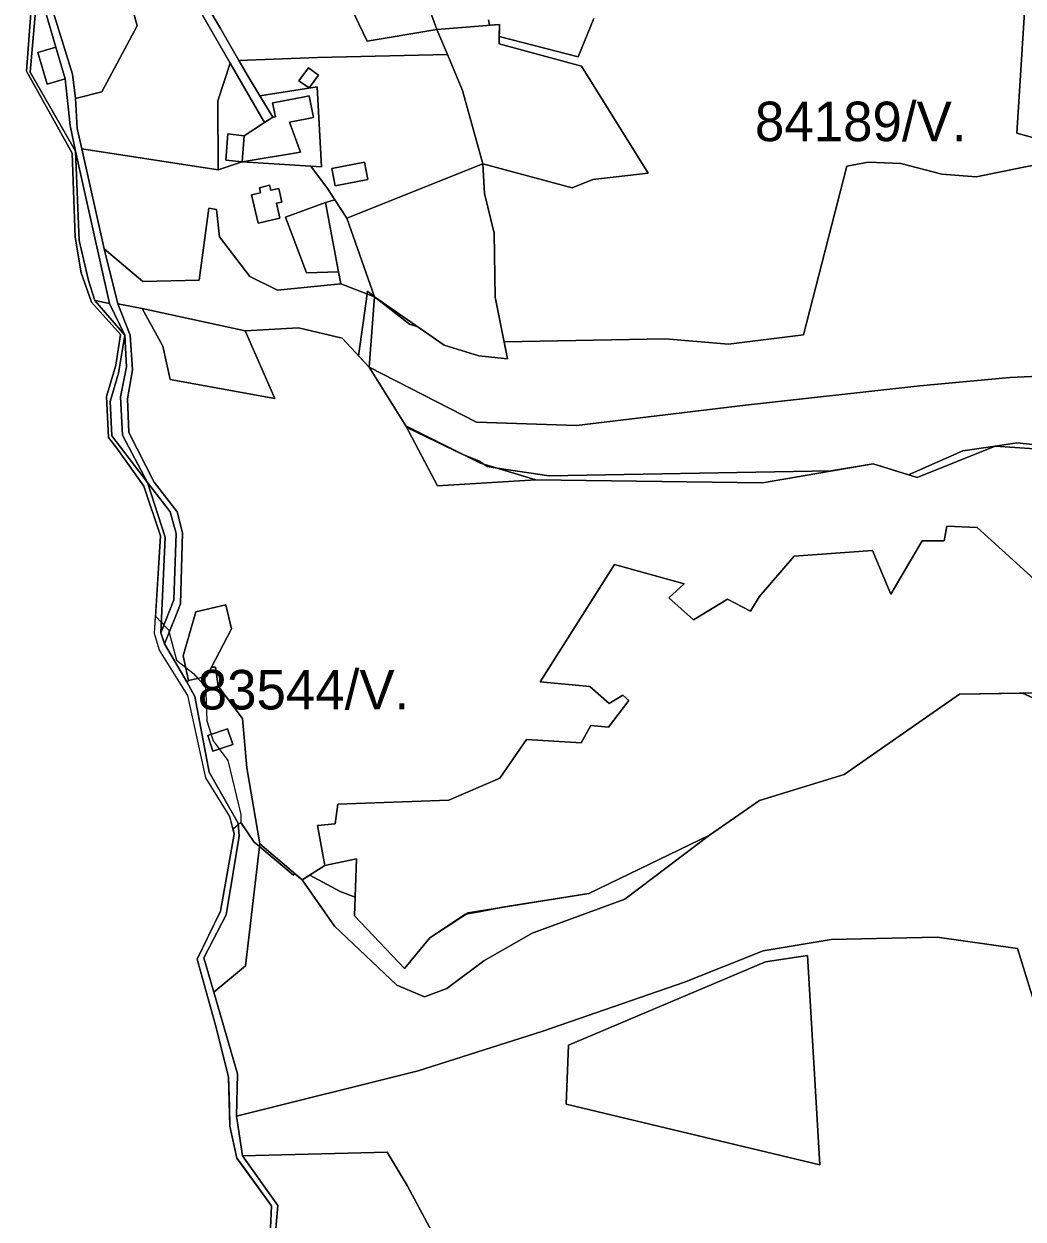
# Model space of a CAD drawing. Extents: x -477304 to -465429, y -1159113 to -1149210.
# Drawn here: x -476570.9 to -476191.6, y -1153194.5 to -1152741 of the extents above; entities that cross this region are included whole.
import ezdxf

# ---------------------------------------------------------------- set-up
doc = ezdxf.new("R2010")
doc.units = 0
for name, color, linetype in [('BPEJ_s', 7, 'Continuous'), ('orna_s', 7, 'Continuous'), ('ostatni_s', 7, 'Continuous'), ('PUPFL_s', 7, 'Continuous'), ('trav_porost_s', 7, 'Continuous'), ('voda_s', 7, 'Continuous'), ('zahrada_s', 7, 'Continuous')]:
    doc.layers.add(name, color=color, linetype=linetype)

msp = doc.modelspace()

# ---------------------------------------------------------------- linework, layer by layer
at = {"layer": 'BPEJ_s'}
for points in [[(-476183, -1152785.5), (-476194, -1152782.5), (-476189, -1152702.5)], [(-476189, -1152702.5), (-476194, -1152782.5), (-476183, -1152785.5)], [(-476567.81, -1152731.72), (-476569.91, -1152758.93), (-476552.56, -1152790.08), (-476551.47, -1152822.01), (-476549.14, -1152835.44), (-476545.27, -1152846.67), (-476534.26, -1152858.87), (-476536.03, -1152870.47), (-476539.49, -1152882.43), (-476538.76, -1152897.9), (-476535.65, -1152901.99), (-476525.32, -1152916.42), (-476519.08, -1152935.21), (-476520.9, -1152965.69), (-476520.9, -1152965.69), (-476518.68, -1152968.1), (-476518.45, -1152968.34), (-476517.71, -1152969.14), (-476516, -1152971), (-476515.74, -1152971.98), (-476513, -1152982.5), (-476509.45, -1152985.23), (-476506.5, -1152987.5), (-476504.83, -1152989.35), (-476502, -1152992.5), (-476501.71, -1152998.04), (-476501.5, -1153005.5), (-476499.79, -1153010.62), (-476499, -1153013), (-476496.71, -1153016.13), (-476493.5, -1153020.5), (-476488.5, -1153041), (-476488.5, -1153044), (-476483.5, -1153051.5), (-476481.47, -1153053.19), (-476468.5, -1153064), (-476468.07, -1153063.46), (-476465.27, -1153065.84), (-476462.38, -1153064), (-476450.8, -1153070.2), (-476445.15, -1153072.31), (-476445.37, -1153079.45), (-476426.41, -1153099.42), (-476416.78, -1153087.77), (-476403.23, -1153078.87), (-476398.04, -1153077.88), (-476389.27, -1153076.21), (-476356.49, -1153071.02), (-476310.66, -1153048.87), (-476291.65, -1153035.67), (-476259.6, -1153025.84), (-476215.79, -1152995.34), (-476191.88, -1152994.93)], [(-476354.5, -1152739), (-476360.5, -1152753.5), (-476390.47, -1152745.78), (-476390.33, -1152741.26), (-476394.13, -1152741.56), (-476394.5, -1152739.5)], [(-476394.5, -1152739.5), (-476394.13, -1152741.56), (-476390.33, -1152741.26), (-476390.47, -1152745.78), (-476360.5, -1152753.5), (-476354.5, -1152739)], [(-476145.5, -1152905), (-476194, -1152900), (-476202.3, -1152901.21), (-476214.5, -1152903), (-476235.1, -1152912.16), (-476248.57, -1152907.9), (-476264.62, -1152910.67), (-476371.5, -1152912.5), (-476391.22, -1152909.56), (-476395, -1152909), (-476396.57, -1152907.95), (-476398, -1152907), (-476403.3, -1152904.79), (-476404, -1152904.5), (-476425.51, -1152894.21), (-476425.88, -1152893.51), (-476439.81, -1152871.28), (-476443.85, -1152866.93), (-476442.15, -1152854.51), (-476440.64, -1152843.5), (-476440.5, -1152842.5), (-476437.82, -1152844.59), (-476424.5, -1152855), (-476421.3, -1152856.02), (-476411.35, -1152862.9), (-476398.18, -1152866.97), (-476387.29, -1152868.06), (-476388.56, -1152861.72), (-476327.5, -1152860.5), (-476303.5, -1152862.5), (-476275, -1152859), (-476258.5, -1152795), (-476250.5, -1152793.5), (-476238, -1152794), (-476222.5, -1152798), (-476209.5, -1152799), (-476182, -1152793.5)], [(-476182, -1152793.5), (-476209.5, -1152799), (-476222.5, -1152798), (-476238, -1152794), (-476250.5, -1152793.5), (-476258.5, -1152795), (-476275, -1152859), (-476303.5, -1152862.5), (-476327.5, -1152860.5), (-476388.56, -1152861.72), (-476387.29, -1152868.06)], [(-476387.29, -1152868.06), (-476398.18, -1152866.97), (-476411.35, -1152862.9), (-476421.3, -1152856.02), (-476424.5, -1152855), (-476437.82, -1152844.59), (-476440.5, -1152842.5), (-476440.64, -1152843.5), (-476442.15, -1152854.51), (-476443.85, -1152866.93), (-476439.81, -1152871.28), (-476425.88, -1152893.51), (-476425.51, -1152894.21), (-476404, -1152904.5), (-476403.3, -1152904.79), (-476398, -1152907), (-476396.57, -1152907.95), (-476395, -1152909), (-476391.22, -1152909.56), (-476371.5, -1152912.5), (-476264.62, -1152910.67), (-476248.57, -1152907.9), (-476235.1, -1152912.16), (-476214.5, -1152903), (-476202.3, -1152901.21), (-476194, -1152900), (-476145.5, -1152905)], [(-476187.7, -1152996.9), (-476191.88, -1152994.93), (-476215.79, -1152995.34), (-476259.6, -1153025.84), (-476291.65, -1153035.67), (-476310.66, -1153048.87), (-476356.49, -1153071.02), (-476389.27, -1153076.21), (-476398.04, -1153077.88), (-476403.23, -1153078.87), (-476416.78, -1153087.77), (-476426.41, -1153099.42), (-476445.37, -1153079.45), (-476445.15, -1153072.31), (-476450.8, -1153070.2), (-476462.38, -1153064), (-476465.27, -1153065.84), (-476468.07, -1153063.46), (-476468.5, -1153064), (-476481.47, -1153053.19), (-476483.5, -1153051.5), (-476488.5, -1153044), (-476489.53, -1153044.88), (-476491.48, -1153046.55), (-476491.01, -1153048.45), (-476496.24, -1153077.74), (-476501.28, -1153088.1), (-476505.09, -1153095.93), (-476503.7, -1153100.91), (-476498.11, -1153120.94), (-476493.2, -1153140.58), (-476492.88, -1153151.81), (-476492.67, -1153159.21), (-476490.01, -1153171.43), (-476488.09, -1153174.09), (-476476.96, -1153189.51), (-476477.29, -1153197.87)], [(-476191.88, -1152994.93), (-476187.7, -1152996.9)]]:
    msp.add_lwpolyline(points, dxfattribs=at)
msp.add_lwpolyline([(-476489.53, -1153044.88), (-476491.48, -1153046.55), (-476492.65, -1153041.77), (-476501.85, -1153027.08), (-476508.63, -1152995.85), (-476519.41, -1152978.6), (-476521.3, -1152972.35), (-476520.9, -1152965.69), (-476520.9, -1152965.69), (-476518.68, -1152968.1), (-476518.45, -1152968.34), (-476517.71, -1152969.14), (-476516, -1152971), (-476515.74, -1152971.98), (-476513, -1152982.5), (-476509.45, -1152985.23), (-476506.5, -1152987.5), (-476504.83, -1152989.35), (-476502, -1152992.5), (-476501.71, -1152998.04), (-476501.5, -1153005.5), (-476499.79, -1153010.62), (-476499, -1153013), (-476496.71, -1153016.13), (-476493.5, -1153020.5), (-476488.5, -1153041), (-476488.5, -1153044)], close=True, dxfattribs=at)
at = {"layer": 'orna_s'}
for points in [[(-476424.8, -1152645.4), (-476425.84, -1152701.17), (-476421.11, -1152723.99), (-476414.17, -1152743.15), (-476440.62, -1152747.55), (-476448.07, -1152731.86), (-476492.05, -1152735.81), (-476492.35, -1152704.81), (-476478.13, -1152702.4), (-476471.19, -1152696.63), (-476478.48, -1152696.5), (-476472.81, -1152648.4), (-476467.38, -1152631.32)], [(-476448.35, -1152814.68), (-476396.66, -1152794.08), (-476396.1, -1152805.37), (-476392.4, -1152820.38), (-476391.98, -1152844.66), (-476387.29, -1152868.06), (-476398.18, -1152866.97), (-476411.35, -1152862.9), (-476437.82, -1152844.59)]]:
    msp.add_lwpolyline(points, close=True, dxfattribs=at)
at = {"layer": 'ostatni_s'}
for points in [[(-476562.08, -1152763.89), (-476555.2, -1152761.87), (-476553.29, -1152779.52), (-476551.25, -1152789.35), (-476568.49, -1152759.38), (-476566.13, -1152731.75), (-476570.87, -1152716.42), (-476569.14, -1152714.66), (-476562.37, -1152717.06), (-476563.56, -1152733.44), (-476558.73, -1152749.83), (-476565.61, -1152751.85)], [(-476555.2, -1152761.87), (-476562.08, -1152763.89), (-476565.61, -1152751.85), (-476558.73, -1152749.83)], [(-476466.47, -1152762.6), (-476462.89, -1152757.73), (-476459.06, -1152760.54), (-476462.64, -1152765.31)], [(-476475.67, -1152770.88), (-476465.06, -1152768.82), (-476462.66, -1152768.36), (-476461, -1152776.59), (-476463.47, -1152777.08), (-476470.03, -1152778.31), (-476465.88, -1152789.68), (-476488.08, -1152793.41), (-476487.31, -1152783.47), (-476479.54, -1152778.48), (-476476.4, -1152776.47), (-476475.41, -1152776.32), (-476476.46, -1152771.03)], [(-476488.08, -1152793.41), (-476494.22, -1152792.73), (-476493.46, -1152782.8), (-476487.31, -1152783.47)], [(-476543.9, -1152846.04), (-476546.3, -1152838.37), (-476549.86, -1152823.16), (-476551.25, -1152789.35), (-476538.37, -1152847.07)], [(-476440.34, -1152800.01), (-476452.79, -1152802.42), (-476454.04, -1152795.94), (-476441.59, -1152793.53)], [(-476477.16, -1152804.14), (-476474.15, -1152803.45), (-476472.95, -1152808.61), (-476474.96, -1152809.07), (-476473.78, -1152814.69), (-476481.9, -1152816.63), (-476484.43, -1152805.9), (-476481.01, -1152805.07), (-476481.45, -1152803.19), (-476477.6, -1152802.25)], [(-476450.63, -1152839.62), (-476451.48, -1152835.09), (-476456.38, -1152808.8), (-476452.87, -1152807.77), (-476448.35, -1152814.68), (-476437.82, -1152844.59)], [(-476538.37, -1152847.07), (-476532.5, -1152859.18), (-476543.9, -1152846.04)], [(-476523.97, -1152915.05), (-476537.49, -1152897.27), (-476538.07, -1152884.24), (-476534.94, -1152873.49), (-476532.5, -1152859.18), (-476531.99, -1152871.1), (-476534.24, -1152882.48), (-476533.47, -1152897.09)], [(-476513.07, -1152934.44), (-476513.99, -1152959.51), (-476518.86, -1152972.11), (-476517.21, -1152935.73), (-476523.97, -1152915.05), (-476515.36, -1152926.21)], [(-476501.52, -1152988.65), (-476508.42, -1152990.11), (-476510.39, -1152980.77), (-476505.59, -1152964.16), (-476494.29, -1152961.41), (-476492.06, -1152970.58), (-476499.63, -1152985.05)], [(-476486.31, -1153023.31), (-476481.35, -1153052.13), (-476486.82, -1153098.41), (-476498.77, -1153108.38), (-476502.52, -1153095.43), (-476494.09, -1153079.04), (-476489.13, -1153049.27), (-476489.58, -1153044.29), (-476500.58, -1153024.93), (-476505.96, -1152996.25), (-476509.04, -1152990.71), (-476508.42, -1152990.11), (-476501.52, -1152988.65), (-476499.63, -1152985.05), (-476498.11, -1152985.06), (-476497.14, -1152992.25), (-476487.94, -1153004.53)], [(-476499.13, -1153016.94), (-476491.63, -1153014.42), (-476493.61, -1153008.54), (-476501.11, -1153011.06)], [(-476501.11, -1153011.06), (-476493.61, -1153008.54), (-476491.63, -1153014.42), (-476499.13, -1153016.94)]]:
    msp.add_lwpolyline(points, close=True, dxfattribs=at)
for points in [[(-476506.9, -1152724.73), (-476496.31, -1152742.79), (-476489.28, -1152754.92), (-476485.79, -1152760.93), (-476481.32, -1152768.33), (-476476.4, -1152776.47), (-476479.54, -1152778.48), (-476492.61, -1152755.92), (-476512.6, -1152721.2)], [(-476561.07, -1152732.37), (-476552.44, -1152760.14), (-476551.29, -1152769.3), (-476550.67, -1152780.67), (-476548.94, -1152788.49), (-476540.39, -1152826.33), (-476535.22, -1152847.27), (-476530.49, -1152859.18), (-476529.59, -1152872.29), (-476531.58, -1152883.35), (-476531.08, -1152896.12), (-476521.42, -1152914.86), (-476512.68, -1152926.12), (-476510.7, -1152934.15), (-476511.4, -1152961.06), (-476513.15, -1152965.59), (-476517.45, -1152976.19), (-476518.86, -1152972.11), (-476513.99, -1152959.51), (-476513.07, -1152934.44), (-476515.36, -1152926.21), (-476523.97, -1152915.05), (-476533.47, -1152897.09), (-476534.24, -1152882.48), (-476531.99, -1152871.1), (-476532.5, -1152859.18), (-476538.37, -1152847.07), (-476551.25, -1152789.35), (-476553.29, -1152779.52), (-476555.2, -1152761.87), (-476558.73, -1152749.83), (-476563.56, -1152733.44)]]:
    msp.add_lwpolyline(points, dxfattribs=at)
at = {"layer": 'PUPFL_s'}
for points in [[(-476163.87, -1152873.72), (-476196.63, -1152875.18), (-476230.81, -1152878.34), (-476296.98, -1152885.68), (-476361.17, -1152893.44), (-476399.05, -1152892.12), (-476439.81, -1152871.28), (-476437.82, -1152844.59), (-476411.35, -1152862.9), (-476398.18, -1152866.97), (-476387.29, -1152868.06), (-476391.98, -1152844.66), (-476392.4, -1152820.38), (-476396.1, -1152805.37), (-476396.66, -1152794.08), (-476362.76, -1152803.27), (-476354.95, -1152800.05), (-476333.91, -1152797.71), (-476359.23, -1152757.08), (-476390.55, -1152748.6), (-476390.33, -1152741.26), (-476414.17, -1152743.15), (-476421.11, -1152723.99)], [(-476183.76, -1153124.12), (-476193.73, -1153091.86), (-476224.3, -1153087.6), (-476264.53, -1153088.47), (-476290.31, -1153092.75), (-476320.21, -1153104.57), (-476373.93, -1153123.2), (-476421.24, -1153138.32), (-476490.14, -1153155.42), (-476489.78, -1153139.43), (-476498.77, -1153108.38), (-476486.82, -1153098.41), (-476481.35, -1153052.13), (-476465.27, -1153065.84), (-476452.95, -1153083.34), (-476429.35, -1153105.72), (-476418.88, -1153110.2), (-476410.32, -1153107.01), (-476396.35, -1153096.51), (-476377.93, -1153086.03), (-476342.8, -1153073.18), (-476310.66, -1153048.87), (-476291.65, -1153035.67), (-476259.6, -1153025.84), (-476215.79, -1152995.34), (-476178.14, -1152994.7)]]:
    msp.add_lwpolyline(points, dxfattribs=at)
for points in [[(-476488.08, -1152793.41), (-476497.12, -1152796.4), (-476497.26, -1152770.21), (-476492.61, -1152755.92), (-476479.54, -1152778.48), (-476487.31, -1152783.47), (-476493.46, -1152782.8), (-476494.22, -1152792.73)], [(-476485.16, -1152836.89), (-476474.63, -1152842.07), (-476450.63, -1152839.62), (-476437.82, -1152844.59), (-476439.81, -1152871.28), (-476450.03, -1152860.28), (-476466.6, -1152856.3), (-476486.86, -1152857.51), (-476525.95, -1152849.05), (-476535.22, -1152847.27), (-476540.39, -1152826.33), (-476525.69, -1152838.74), (-476504.36, -1152838.24), (-476500.64, -1152810.93), (-476497.73, -1152811.49), (-476496.61, -1152821.85)], [(-476290.59, -1152915.16), (-476376.53, -1152913.98), (-476397.58, -1152907.65), (-476425.88, -1152893.51), (-476439.81, -1152871.28), (-476399.05, -1152892.12), (-476361.17, -1152893.44), (-476296.98, -1152885.68), (-476230.81, -1152878.34), (-476196.63, -1152875.18), (-476163.87, -1152873.72), (-476141.62, -1152874.59), (-476110.83, -1152874.53), (-476094.77, -1152885.67), (-476096.02, -1152886.18), (-476127.83, -1152880.43), (-476142, -1152889.67), (-476142.53, -1152905.27), (-476202.3, -1152901.21), (-476231.89, -1152913.17), (-476248.57, -1152907.9)], [(-476397.58, -1152907.65), (-476376.53, -1152913.98), (-476413.93, -1152916.28), (-476425.88, -1152893.51)], [(-476402.31, -1153078.27), (-476356.49, -1153071.02), (-476310.66, -1153048.87), (-476342.8, -1153073.18), (-476377.93, -1153086.03), (-476396.35, -1153096.51), (-476410.32, -1153107.01), (-476418.88, -1153110.2), (-476429.35, -1153105.72), (-476452.95, -1153083.34), (-476465.27, -1153065.84), (-476456.65, -1153060.35), (-476444.69, -1153057.83), (-476445.37, -1153079.45), (-476426.41, -1153099.42), (-476416.78, -1153087.77)], [(-476333.46, -1153213.17), (-476348.76, -1153204.42), (-476350.46, -1153205.59), (-476354.47, -1153208.34), (-476409.37, -1153211.76), (-476425.36, -1153181.8), (-476432.95, -1153169.09), (-476487.9, -1153170.54), (-476490.14, -1153155.42), (-476421.24, -1153138.32), (-476373.93, -1153123.2), (-476320.21, -1153104.57), (-476290.31, -1153092.75), (-476264.53, -1153088.47), (-476224.3, -1153087.6), (-476193.73, -1153091.86), (-476183.76, -1153124.12), (-476173.13, -1153165.8), (-476161.23, -1153190.7), (-476157.59, -1153196.3), (-476305.47, -1153241.12), (-476320.95, -1153249.89), (-476326.21, -1153247.82), (-476320.61, -1153240.93)], [(-476273.43, -1153094.46), (-476289.47, -1153096.9), (-476364.18, -1153128.52), (-476365, -1153150.9), (-476268.81, -1153173.98)], [(-476365, -1153150.9), (-476364.18, -1153128.52), (-476289.47, -1153096.9), (-476273.43, -1153094.46), (-476268.81, -1153173.98)], [(-476425.36, -1153181.8), (-476409.37, -1153211.76), (-476433.36, -1153199.63), (-476439.63, -1153201.87), (-476474.05, -1153228.49), (-476476.82, -1153215.58), (-476474.44, -1153189.34), (-476487.9, -1153170.54), (-476432.95, -1153169.09)]]:
    msp.add_lwpolyline(points, close=True, dxfattribs=at)
at = {"layer": 'trav_porost_s'}
for points in [[(-476548.59, -1152723.31), (-476544.56, -1152718.44), (-476540.67, -1152711.02), (-476540.77, -1152717.6), (-476534.04, -1152717.7), (-476529.22, -1152705.14), (-476529.13, -1152699.31), (-476538.59, -1152699.17), (-476535.98, -1152681.79), (-476527.8, -1152683.3), (-476522.62, -1152701.2), (-476512.6, -1152721.2), (-476492.61, -1152755.92), (-476497.26, -1152770.21), (-476497.12, -1152796.4), (-476548.94, -1152788.49), (-476550.67, -1152780.67), (-476551.29, -1152769.3), (-476541.24, -1152766.75), (-476527.91, -1152741.71), (-476533.3, -1152721.51)], [(-476503.24, -1152701.75), (-476478.78, -1152699.07), (-476478.48, -1152696.5), (-476471.19, -1152696.63), (-476478.13, -1152702.4), (-476492.35, -1152704.81), (-476492.05, -1152735.81), (-476448.07, -1152731.86), (-476440.62, -1152747.55), (-476414.17, -1152743.15), (-476410.09, -1152752.63), (-476459.47, -1152753.78), (-476489.28, -1152754.92), (-476496.31, -1152742.79), (-476506.9, -1152724.73), (-476507.22, -1152711.78)], [(-476552.44, -1152760.14), (-476561.07, -1152732.37), (-476560.33, -1152722.68), (-476548.59, -1152723.31), (-476533.3, -1152721.51), (-476527.91, -1152741.71), (-476541.24, -1152766.75), (-476551.29, -1152769.3)], [(-476390.33, -1152741.26), (-476390.55, -1152748.6), (-476359.23, -1152757.08), (-476333.91, -1152797.71), (-476354.95, -1152800.05), (-476362.76, -1152803.27), (-476396.66, -1152794.08), (-476404.45, -1152766.31), (-476410.09, -1152752.63), (-476414.17, -1152743.15)], [(-476452.87, -1152807.77), (-476455.67, -1152803.49), (-476461.92, -1152795.03), (-476457.94, -1152795.28), (-476459.56, -1152764.93), (-476481.32, -1152768.33), (-476485.79, -1152760.93), (-476489.28, -1152754.92), (-476459.47, -1152753.78), (-476410.09, -1152752.63), (-476404.45, -1152766.31), (-476396.66, -1152794.08), (-476448.35, -1152814.68)], [(-476462.89, -1152757.73), (-476466.47, -1152762.6), (-476462.64, -1152765.31), (-476459.06, -1152760.54)], [(-476465.88, -1152789.68), (-476470.03, -1152778.31), (-476463.47, -1152777.08), (-476461, -1152776.59), (-476462.66, -1152768.36), (-476465.06, -1152768.82), (-476475.67, -1152770.88), (-476476.46, -1152771.03), (-476475.41, -1152776.32), (-476476.4, -1152776.47), (-476481.32, -1152768.33), (-476459.56, -1152764.93), (-476457.94, -1152795.28), (-476461.92, -1152795.03), (-476488.08, -1152793.41)], [(-476504.36, -1152838.24), (-476525.69, -1152838.74), (-476540.39, -1152826.33), (-476548.94, -1152788.49), (-476497.12, -1152796.4), (-476488.08, -1152793.41), (-476461.92, -1152795.03), (-476455.67, -1152803.49), (-476452.87, -1152807.77), (-476456.38, -1152808.8), (-476471.62, -1152814.33), (-476463.67, -1152835.5), (-476451.48, -1152835.09), (-476450.63, -1152839.62), (-476474.63, -1152842.07), (-476485.16, -1152836.89), (-476496.61, -1152821.85), (-476497.73, -1152811.49), (-476500.64, -1152810.93)], [(-476452.79, -1152802.42), (-476440.34, -1152800.01), (-476441.59, -1152793.53), (-476454.04, -1152795.94)], [(-476477.6, -1152802.25), (-476481.45, -1152803.19), (-476481.01, -1152805.07), (-476484.43, -1152805.9), (-476481.9, -1152816.63), (-476473.78, -1152814.69), (-476474.96, -1152809.07), (-476472.95, -1152808.61), (-476474.15, -1152803.45), (-476477.16, -1152804.14)], [(-476515.34, -1152876.01), (-476518.18, -1152863.32), (-476525.95, -1152849.05), (-476486.86, -1152857.51), (-476475.64, -1152883.16)]]:
    msp.add_lwpolyline(points, close=True, dxfattribs=at)
for points in [[(-476180.66, -1152957.87), (-476209.13, -1152932.07), (-476220.55, -1152931.63), (-476221.61, -1152937.17), (-476229.93, -1152937.2), (-476241.8, -1152957.42), (-476248.74, -1152940.84), (-476278.55, -1152943), (-476291.82, -1152958.46), (-476295.04, -1152963.86), (-476303.77, -1152959.33), (-476316.71, -1152967.11), (-476326.06, -1152958.82), (-476320.29, -1152953.5), (-476346.69, -1152946.13), (-476374.93, -1152990.64), (-476356.04, -1152992.4), (-476348.76, -1152998.9), (-476343.5, -1152995.76), (-476341.31, -1152997.72), (-476348.98, -1153007.81), (-476355.65, -1153007.25), (-476359.34, -1153013.86), (-476380.08, -1153012.54), (-476390.22, -1153027.22), (-476409.56, -1153035.53), (-476451.69, -1153037.02), (-476452.73, -1153044.55), (-476459.45, -1153045.22), (-476456.65, -1153060.35), (-476465.27, -1153065.84), (-476481.35, -1153052.13), (-476486.31, -1153023.31), (-476487.94, -1153004.53), (-476497.14, -1152992.25), (-476498.11, -1152985.06), (-476499.63, -1152985.05), (-476492.06, -1152970.58), (-476494.29, -1152961.41), (-476505.59, -1152964.16), (-476510.39, -1152980.77), (-476508.42, -1152990.11), (-476509.04, -1152990.71), (-476517.45, -1152976.19), (-476513.15, -1152965.59), (-476511.4, -1152961.06), (-476510.7, -1152934.15), (-476512.68, -1152926.12), (-476521.42, -1152914.86), (-476531.08, -1152896.12), (-476531.58, -1152883.35), (-476529.59, -1152872.29), (-476530.49, -1152859.18), (-476535.22, -1152847.27), (-476525.95, -1152849.05), (-476518.18, -1152863.32), (-476515.34, -1152876.01), (-476475.64, -1152883.16), (-476486.86, -1152857.51), (-476466.6, -1152856.3), (-476450.03, -1152860.28), (-476439.81, -1152871.28), (-476425.88, -1152893.51), (-476413.93, -1152916.28), (-476376.53, -1152913.98), (-476290.59, -1152915.16), (-476248.57, -1152907.9), (-476231.89, -1152913.17), (-476202.3, -1152901.21), (-476142.53, -1152905.27)], [(-476178.14, -1152994.7), (-476215.79, -1152995.34), (-476259.6, -1153025.84), (-476291.65, -1153035.67), (-476310.66, -1153048.87), (-476356.49, -1153071.02), (-476402.31, -1153078.27), (-476416.78, -1153087.77), (-476426.41, -1153099.42), (-476445.37, -1153079.45), (-476444.69, -1153057.83), (-476456.65, -1153060.35), (-476459.45, -1153045.22), (-476452.73, -1153044.55), (-476451.69, -1153037.02), (-476409.56, -1153035.53), (-476390.22, -1153027.22), (-476380.08, -1153012.54), (-476359.34, -1153013.86), (-476355.65, -1153007.25), (-476348.98, -1153007.81), (-476341.31, -1152997.72), (-476343.5, -1152995.76), (-476348.76, -1152998.9), (-476356.04, -1152992.4), (-476374.93, -1152990.64), (-476346.69, -1152946.13), (-476320.29, -1152953.5), (-476326.06, -1152958.82), (-476316.71, -1152967.11), (-476303.77, -1152959.33), (-476295.04, -1152963.86), (-476291.82, -1152958.46), (-476278.55, -1152943), (-476248.74, -1152940.84), (-476241.8, -1152957.42), (-476229.93, -1152937.2), (-476221.61, -1152937.17), (-476220.55, -1152931.63), (-476209.13, -1152932.07), (-476180.66, -1152957.87)]]:
    msp.add_lwpolyline(points, dxfattribs=at)
at = {"layer": 'voda_s'}
for points in [[(-476477.29, -1153197.87), (-476476.96, -1153189.51), (-476490.01, -1153171.43), (-476492.67, -1153159.21), (-476493.2, -1153140.58), (-476498.11, -1153120.94), (-476505.09, -1153095.93), (-476496.24, -1153077.74), (-476491.01, -1153048.45), (-476492.65, -1153041.77), (-476501.85, -1153027.08), (-476508.63, -1152995.85), (-476519.41, -1152978.6), (-476521.3, -1152972.35), (-476519.08, -1152935.21), (-476525.32, -1152916.42), (-476535.65, -1152901.99), (-476538.76, -1152897.9), (-476539.49, -1152882.43), (-476536.03, -1152870.47), (-476534.26, -1152858.87), (-476545.27, -1152846.67), (-476549.14, -1152835.44), (-476551.47, -1152822.01), (-476552.56, -1152790.08), (-476569.91, -1152758.93), (-476567.81, -1152731.72)], [(-476566.13, -1152731.75), (-476568.49, -1152759.38), (-476551.25, -1152789.35), (-476549.86, -1152823.16), (-476546.3, -1152838.37)], [(-476546.3, -1152838.37), (-476543.9, -1152846.04), (-476532.5, -1152859.18), (-476534.94, -1152873.49), (-476538.07, -1152884.24), (-476537.49, -1152897.27), (-476523.97, -1152915.05), (-476517.21, -1152935.73), (-476518.86, -1152972.11), (-476517.45, -1152976.19), (-476509.04, -1152990.71), (-476505.96, -1152996.25), (-476500.58, -1153024.93), (-476489.58, -1153044.29), (-476489.13, -1153049.27), (-476494.09, -1153079.04), (-476502.52, -1153095.43), (-476498.77, -1153108.38), (-476489.78, -1153139.43), (-476490.14, -1153155.42), (-476487.9, -1153170.54), (-476474.44, -1153189.34), (-476476.82, -1153215.58)]]:
    msp.add_lwpolyline(points, dxfattribs=at)
at = {"layer": 'zahrada_s'}
msp.add_lwpolyline([(-476463.67, -1152835.5), (-476471.62, -1152814.33), (-476456.38, -1152808.8), (-476451.48, -1152835.09)], close=True, dxfattribs=at)

# ---------------------------------------------------------------- texts
at = {"layer": 'BPEJ_s'}
for s, p in [('84189/V.', (-476293.42, -1152785.53)), ('83544/V.', (-476504.9, -1153001.15))]:
    msp.add_text(s, height=15, dxfattribs=at).set_placement(p)

doc.saveas('drawing.dxf')
